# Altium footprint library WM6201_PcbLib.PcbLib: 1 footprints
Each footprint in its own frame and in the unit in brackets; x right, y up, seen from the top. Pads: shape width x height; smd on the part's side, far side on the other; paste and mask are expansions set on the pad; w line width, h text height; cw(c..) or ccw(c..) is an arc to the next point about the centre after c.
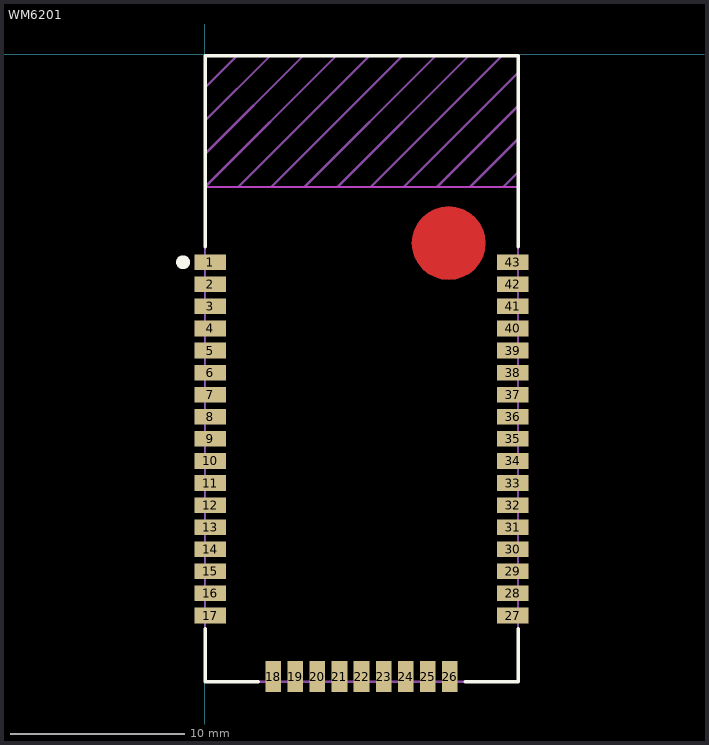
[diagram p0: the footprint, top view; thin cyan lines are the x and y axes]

## WM6201 [mm]
height 2.75
pads (43):
  rect 1.8x0.9 smd: 1(0.317,-11.961) 2(0.317,-13.231) 3(0.317,-14.501) 4(0.317,-15.771) 5(0.317,-17.041) 6(0.317,-18.311) 7(0.317,-19.581) 8(0.317,-20.851) 9(0.317,-22.121) 10(0.317,-23.391) 11(0.317,-24.661) 12(0.317,-25.931) 13(0.317,-27.201) 14(0.317,-28.471) 15(0.317,-29.741) 16(0.317,-31.011) 17(0.317,-32.281) 27(17.717,-32.281) 28(17.717,-31.011) 29(17.717,-29.741) 30(17.717,-28.471) 31(17.717,-27.201) 32(17.717,-25.931) 33(17.717,-24.661) 34(17.717,-23.391) 35(17.717,-22.121) 36(17.717,-20.851) 37(17.717,-19.581) 38(17.717,-18.311) 39(17.717,-17.041) 40(17.717,-15.771) 41(17.717,-14.501) 42(17.717,-13.231) 43(17.717,-11.961)
  rect 0.9x1.8 smd: 18(3.937,-35.791) 19(5.207,-35.791) 20(6.477,-35.791) 21(7.747,-35.791) 22(9.017,-35.791) 23(10.287,-35.791) 24(11.557,-35.791) 25(12.827,-35.791) 26(14.097,-35.791)
Top Layer:
  pour cut-out: 14.024,-12.971 13.613,-12.93 13.217,-12.81 12.852,-12.615 12.532,-12.353 12.27,-12.033 12.075,-11.668 11.955,-11.272 11.914,-10.861 11.955,-10.449 12.075,-10.053 12.27,-9.688 12.532,-9.368 12.852,-9.106 13.217,-8.911 13.613,-8.791 14.024,-8.75 14.436,-8.791 14.832,-8.911 15.197,-9.106 15.517,-9.368 15.779,-9.688 15.974,-10.053 16.094,-10.449 16.135,-10.861 16.094,-11.272 15.974,-11.668 15.779,-12.033 15.517,-12.353 15.197,-12.615 14.832,-12.81 14.436,-12.93
Top Overlay:
  circle w0.4: c-1.253,-11.961 r0.2
  lines w0.2: 0.017,-33.043 0.017,-36.091 3.065,-36.091 ; 0.017,-11.072 0.017,-0.091 18.017,-0.091 18.017,-11.072 ; 14.969,-36.091 18.017,-36.091 18.017,-33.043
Keep-Out Layer:
  lines w0.127: 0.017,-7.641 18.017,-7.641 18.017,-0.091 0.017,-0.091 0.017,-7.641
Mechanical 15:
  lines w0.127: 0.017,-5.736 5.662,-0.091 ; 0.017,-3.831 3.757,-0.091 ; 0.017,-1.926 1.852,-0.091 ; 1.922,-7.641 9.472,-0.091 ; 3.827,-7.641 11.377,-0.091 ; 5.732,-7.641 13.282,-0.091 ; 7.567,-0.091 0.017,-7.641 18.017,-7.641 ; 7.637,-7.641 15.187,-0.091 ; 9.542,-7.641 17.092,-0.091 ; 11.447,-7.641 18.017,-1.071 ; 13.352,-7.641 18.017,-2.976 ; 15.257,-7.641 18.017,-4.881 ; 17.162,-7.641 18.017,-6.786 ; 0.017,-36.091 0.017,-0.091 18.017,-0.091 18.017,-36.091 0.017,-36.091
  text "Antenna Are  keepout on all layer" at 3.065,-4.087 h0.51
